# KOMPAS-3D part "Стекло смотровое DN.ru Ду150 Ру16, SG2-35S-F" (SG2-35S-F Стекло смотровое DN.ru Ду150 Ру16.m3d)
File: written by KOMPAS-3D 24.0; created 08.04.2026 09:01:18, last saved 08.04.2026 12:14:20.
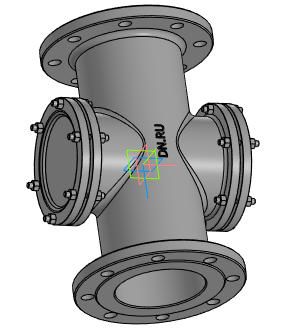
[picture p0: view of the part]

Document properties: Автор: Main; Полное имя файла: SG2-35S-FСтекло смотровое DN.ru Ду150 Ру16 (3d).cdw

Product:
- Body: Тело 1  | qty 1
    Масса: 46.781742
- Part/product: Стекло смотровое DN.ru Ду150 Ру16  | designation SG2-35S-F
    Масса: 42
    Раздел спецификации: Прочие изделия
    Форматы листов документа: A4
    Примечание: D500-00101

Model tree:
1. Операция без истории:1

Expressions: SG2-35S-F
